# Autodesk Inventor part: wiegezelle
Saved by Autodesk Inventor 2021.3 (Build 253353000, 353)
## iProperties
Created: 2023-07
Part Number: wiegezelle
Material: Generic
Document SubType Name: Modeling
Designer: AdminForWorker
Density: 1 g/cm^3
Appearance: Default
Title: wiegezelle v4
Author: AdminForWorker
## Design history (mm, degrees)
feature "Body1"
body "Solid1"
